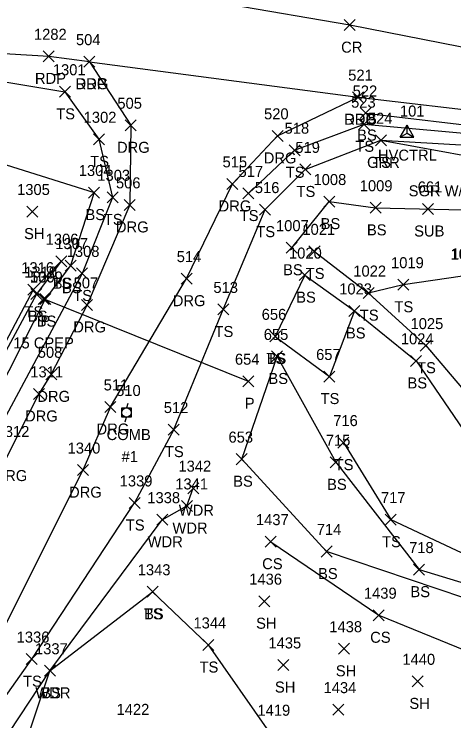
# Model space of a CAD drawing. Extents: x 1485624 to 1495982, y 886445 to 890805.
# Drawn here: x 1495597.7 to 1495677.5, y 890477.2 to 890605.4 of the extents above; entities that cross this region are included whole.
import ezdxf

# ---------------------------------------------------------------- set-up
doc = ezdxf.new("R2010")
doc.units = 0
for name, color, linetype in [('C_A', 7, 'Continuous'), ('C_I', 7, 'Continuous'), ('CPSM', 7, 'Continuous'), ('D_A', 7, 'Continuous'), ('D_C', 7, 'Continuous'), ('D_I', 7, 'Continuous'), ('D_TIC', 7, 'Continuous'), ('DCP', 7, 'Continuous'), ('L_A', 7, 'Continuous'), ('L_I', 7, 'Continuous'), ('L_TIC', 7, 'Continuous'), ('LAWA', 7, 'Continuous'), ('LELB', 7, 'Continuous'), ('P_A', 7, 'Continuous'), ('P_I', 7, 'Continuous'), ('P_TIC', 7, 'Continuous'), ('PET', 7, 'Continuous'), ('PRC', 7, 'Continuous'), ('R_A', 7, 'Continuous'), ('R_C', 7, 'Continuous'), ('R_I', 7, 'Continuous'), ('R_TIC', 7, 'Continuous'), ('RDG', 7, 'Continuous'), ('RGR', 7, 'Continuous'), ('U_A', 7, 'Continuous'), ('U_C', 7, 'Continuous'), ('U_I', 7, 'Continuous'), ('U_TIC', 7, 'Continuous'), ('UP', 7, 'Continuous')]:
    doc.layers.add(name, color=color, linetype=linetype)

msp = doc.modelspace()

# ---------------------------------------------------------------- linework, layer by layer
at = {"layer": 'CPSM'}
for p, q in [((1495667.79, 890583.11), (1495669.04, 890585.28)), ((1495670.29, 890583.11), (1495669.04, 890585.28)), ((1495669.04, 890583.84), (1495669.04, 890585.28)), ((1495667.79, 890583.11), (1495669.04, 890583.84)), ((1495669.04, 890583.84), (1495669.04, 890583.84)), ((1495669.04, 890583.84), (1495670.29, 890583.11)), ((1495667.79, 890583.11), (1495670.29, 890583.11))]:
    msp.add_line(p, q, dxfattribs=at)
at = {"layer": 'D_TIC'}
for points in [[(1495602.05, 890552.75), (1495604.05, 890554.75)], [(1495604.05, 890552.75), (1495602.05, 890554.75)], [(1495639.18, 890537.8), (1495641.18, 890539.8)], [(1495641.18, 890537.8), (1495639.18, 890539.8)]]:
    msp.add_lwpolyline(points, dxfattribs=at)
at = {"layer": 'DCP'}
msp.add_lwpolyline([(1495603.05, 890553.75), (1495640.18, 890538.8)], dxfattribs=at)
at = {"layer": 'L_TIC'}
for points in [[(1495605.9, 890590.34), (1495607.9, 890592.34)], [(1495607.9, 890590.34), (1495605.9, 890592.34)], [(1495660.52, 890586.48), (1495662.52, 890588.48)], [(1495662.52, 890586.48), (1495660.52, 890588.48)], [(1495660.23, 890584.45), (1495662.23, 890586.45)], [(1495662.23, 890584.45), (1495660.23, 890586.45)], [(1495612.07, 890581.71), (1495614.07, 890583.71)], [(1495614.07, 890581.71), (1495612.07, 890583.71)], [(1495663.27, 890581.53), (1495665.27, 890583.53)], [(1495665.27, 890581.53), (1495663.27, 890583.53)], [(1495647.59, 890579.73), (1495649.59, 890581.73)], [(1495649.59, 890579.73), (1495647.59, 890581.73)], [(1495649.54, 890576.25), (1495651.54, 890578.25)], [(1495651.54, 890576.25), (1495649.54, 890578.25)], [(1495611.18, 890572.05), (1495613.18, 890574.05)], [(1495613.18, 890572.05), (1495611.18, 890574.05)], [(1495639.23, 890571.88), (1495641.23, 890573.88)], [(1495641.23, 890571.88), (1495639.23, 890573.88)], [(1495614.55, 890571.18), (1495616.55, 890573.18)], [(1495616.55, 890571.18), (1495614.55, 890573.18)], [(1495653.89, 890570.41), (1495655.89, 890572.41)], [(1495655.89, 890570.41), (1495653.89, 890572.41)], [(1495642.24, 890568.95), (1495644.24, 890570.95)], [(1495644.24, 890568.95), (1495642.24, 890570.95)], [(1495642.24, 890568.95), (1495644.24, 890570.95)], [(1495644.24, 890568.95), (1495642.24, 890570.95)], [(1495662.3, 890569.28), (1495664.3, 890571.28)], [(1495664.3, 890569.28), (1495662.3, 890571.28)], [(1495599.98, 890568.6), (1495601.98, 890570.6)], [(1495601.98, 890568.6), (1495599.98, 890570.6)], [(1495647.08, 890562.04), (1495649.08, 890564.04)], [(1495649.08, 890562.04), (1495647.08, 890564.04)], [(1495651.22, 890561.37), (1495653.22, 890563.37)], [(1495653.22, 890561.37), (1495651.22, 890563.37)], [(1495605.23, 890559.58), (1495607.23, 890561.58)], [(1495607.23, 890559.58), (1495605.23, 890561.58)], [(1495605.23, 890559.58), (1495607.23, 890561.58)], [(1495607.23, 890559.58), (1495605.23, 890561.58)], [(1495606.91, 890558.78), (1495608.91, 890560.78)], [(1495608.91, 890558.78), (1495606.91, 890560.78)], [(1495609, 890557.37), (1495611, 890559.37)], [(1495611, 890557.37), (1495609, 890559.37)], [(1495649.44, 890557.06), (1495651.44, 890559.06)], [(1495651.44, 890557.06), (1495649.44, 890559.06)], [(1495667.33, 890555.32), (1495669.33, 890557.32)], [(1495669.33, 890555.32), (1495667.33, 890557.32)], [(1495600.14, 890554.41), (1495602.14, 890556.41)], [(1495602.14, 890554.41), (1495600.14, 890556.41)], [(1495600.73, 890553.61), (1495602.73, 890555.61)], [(1495602.73, 890553.61), (1495600.73, 890555.61)], [(1495661.04, 890553.8), (1495663.04, 890555.8)], [(1495663.04, 890553.8), (1495661.04, 890555.8)], [(1495661.04, 890553.8), (1495663.04, 890555.8)], [(1495663.04, 890553.8), (1495661.04, 890555.8)], [(1495602.33, 890552.72), (1495604.33, 890554.72)], [(1495604.33, 890552.72), (1495602.33, 890554.72)], [(1495634.65, 890550.83), (1495636.65, 890552.83)], [(1495636.65, 890550.83), (1495634.65, 890552.83)], [(1495658.47, 890550.56), (1495660.47, 890552.56)], [(1495660.47, 890550.56), (1495658.47, 890552.56)], [(1495644.09, 890545.94), (1495646.09, 890547.94)], [(1495646.09, 890545.94), (1495644.09, 890547.94)], [(1495644.09, 890545.94), (1495646.09, 890547.94)], [(1495646.09, 890545.94), (1495644.09, 890547.94)], [(1495671.43, 890544.26), (1495673.43, 890546.26)], [(1495673.43, 890544.26), (1495671.43, 890546.26)], [(1495644.41, 890542.3), (1495646.41, 890544.3)], [(1495646.41, 890542.3), (1495644.41, 890544.3)], [(1495669.67, 890541.5), (1495671.67, 890543.5)], [(1495671.67, 890541.5), (1495669.67, 890543.5)], [(1495653.92, 890538.66), (1495655.92, 890540.66)], [(1495655.92, 890538.66), (1495653.92, 890540.66)], [(1495625.65, 890529.03), (1495627.65, 890531.03)], [(1495627.65, 890529.03), (1495625.65, 890531.03)], [(1495656.47, 890526.66), (1495658.47, 890528.66)], [(1495658.47, 890526.66), (1495656.47, 890528.66)], [(1495638, 890523.66), (1495640, 890525.66)], [(1495640, 890523.66), (1495638, 890525.66)], [(1495638, 890523.66), (1495640, 890525.66)], [(1495640, 890523.66), (1495638, 890525.66)], [(1495655.07, 890523.09), (1495657.07, 890525.09)], [(1495657.07, 890523.09), (1495655.07, 890525.09)], [(1495629.21, 890518.39), (1495631.21, 890520.39)], [(1495631.21, 890518.39), (1495629.21, 890520.39)], [(1495618.54, 890515.71), (1495620.54, 890517.71)], [(1495620.54, 890515.71), (1495618.54, 890517.71)], [(1495628.05, 890515.16), (1495630.05, 890517.16)], [(1495630.05, 890515.16), (1495628.05, 890517.16)], [(1495623.56, 890512.67), (1495625.56, 890514.67)], [(1495625.56, 890512.67), (1495623.56, 890514.67)], [(1495665.08, 890512.68), (1495667.08, 890514.68)], [(1495667.08, 890512.68), (1495665.08, 890514.68)], [(1495643.28, 890508.68), (1495645.28, 890510.68)], [(1495645.28, 890508.68), (1495643.28, 890510.68)], [(1495653.42, 890506.9), (1495655.42, 890508.9)], [(1495655.42, 890506.9), (1495653.42, 890508.9)], [(1495653.42, 890506.9), (1495655.42, 890508.9)], [(1495655.42, 890506.9), (1495653.42, 890508.9)], [(1495670.2, 890503.61), (1495672.2, 890505.61)], [(1495672.2, 890503.61), (1495670.2, 890505.61)], [(1495621.82, 890499.59), (1495623.82, 890501.59)], [(1495623.82, 890499.59), (1495621.82, 890501.59)], [(1495621.82, 890499.59), (1495623.82, 890501.59)], [(1495623.82, 890499.59), (1495621.82, 890501.59)], [(1495642.12, 890497.88), (1495644.12, 890499.88)], [(1495644.12, 890497.88), (1495642.12, 890499.88)], [(1495662.89, 890495.33), (1495664.89, 890497.33)], [(1495664.89, 890495.33), (1495662.89, 890497.33)], [(1495631.93, 890489.93), (1495633.93, 890491.93)], [(1495633.93, 890489.93), (1495631.93, 890491.93)], [(1495656.6, 890489.25), (1495658.6, 890491.25)], [(1495658.6, 890489.25), (1495656.6, 890491.25)], [(1495599.88, 890487.37), (1495601.88, 890489.37)], [(1495601.88, 890487.37), (1495599.88, 890489.37)], [(1495645.54, 890486.3), (1495647.54, 890488.3)], [(1495647.54, 890486.3), (1495645.54, 890488.3)], [(1495603.16, 890485.25), (1495605.16, 890487.25)], [(1495605.16, 890485.25), (1495603.16, 890487.25)], [(1495603.16, 890485.25), (1495605.16, 890487.25)], [(1495605.16, 890485.25), (1495603.16, 890487.25)], [(1495669.96, 890483.33), (1495671.96, 890485.33)], [(1495671.96, 890483.33), (1495669.96, 890485.33)], [(1495655.57, 890478.19), (1495657.57, 890480.19)], [(1495657.57, 890478.19), (1495655.57, 890480.19)]]:
    msp.add_lwpolyline(points, dxfattribs=at)
at = {"layer": 'LAWA'}
msp.add_lwpolyline([(1495593.77, 890455.29), (1495604.16, 890486.25), (1495624.56, 890513.67), (1495629.05, 890516.16), (1495630.21, 890519.39)], dxfattribs=at)
at = {"layer": 'LELB'}
for points in [[(1495490.02, 890593.49), (1495517.04, 890595.05), (1495546.88, 890595.72), (1495587.58, 890594.51), (1495606.9, 890591.34), (1495613.07, 890582.71), (1495615.55, 890572.18), (1495610, 890558.37), (1495592.88, 890526.49), (1495577.8, 890499.74), (1495564.37, 890470.63)], [(1495491.22, 890587.26), (1495516.29, 890586.39), (1495547.35, 890588.58), (1495580.2, 890583.12), (1495612.18, 890573.05), (1495607.91, 890559.78), (1495603.33, 890553.72), (1495590.06, 890527.67), (1495576, 890500.47), (1495561.43, 890471.67)], [(1495661.52, 890587.48), (1495685.12, 890584.7), (1495703.82, 890581.92), (1495734.08, 890574), (1495763.24, 890565.13), (1495792.96, 890554.55)], [(1495640.23, 890572.88), (1495648.59, 890580.73), (1495661.23, 890585.45), (1495684.75, 890583.37), (1495703.16, 890579.81), (1495734, 890573.11), (1495763.03, 890564.51), (1495792.96, 890554.55)], [(1495643.24, 890569.95), (1495650.54, 890577.25), (1495664.27, 890582.53), (1495690.14, 890577.82), (1495701.7, 890574.71), (1495732.13, 890567.79), (1495761.45, 890557.4), (1495788.87, 890547.86), (1495821.91, 890535.22), (1495855.28, 890520.02)], [(1495648.08, 890563.04), (1495654.89, 890571.41), (1495663.3, 890570.28), (1495684.61, 890569.8), (1495706.27, 890563.36), (1495726.08, 890556.74), (1495739.05, 890554.91)], [(1495626.65, 890530.03), (1495635.65, 890551.83), (1495643.24, 890569.95)], [(1495652.22, 890562.37), (1495662.04, 890554.8)], [(1495606.23, 890560.58), (1495601.14, 890555.41), (1495586.75, 890528.42), (1495573.49, 890501.46), (1495559.15, 890472.78)], [(1495606.23, 890560.58), (1495601.73, 890554.61), (1495587.51, 890528.3), (1495574.69, 890500.59), (1495560.18, 890472.05)], [(1495650.44, 890558.06), (1495645.09, 890546.94)], [(1495650.44, 890558.06), (1495659.47, 890551.56), (1495670.67, 890542.5), (1495680.95, 890527.45), (1495694.72, 890514.02), (1495701.89, 890508.36)], [(1495739.03, 890547.65), (1495724.1, 890552.5), (1495699.75, 890551.1), (1495679.27, 890557.9), (1495679.11, 890557.89), (1495668.33, 890556.32), (1495662.04, 890554.8), (1495672.43, 890545.26), (1495683.67, 890532.06), (1495695.19, 890516.26), (1495707.45, 890511.95), (1495709.18, 890508.83), (1495715.54, 890502.47), (1495718.87, 890501.79), (1495723.73, 890502.35)], [(1495659.47, 890551.56), (1495654.92, 890539.66)], [(1495645.09, 890546.94), (1495654.92, 890539.66)], [(1495639, 890524.66), (1495645.41, 890543.3), (1495656.07, 890524.09), (1495671.2, 890504.61), (1495691.33, 890498.5), (1495709.49, 890487.2)], [(1495626.65, 890530.03), (1495619.54, 890516.71)], [(1495657.47, 890527.66), (1495666.08, 890513.68), (1495691.78, 890501.67), (1495709.49, 890487.2)], [(1495639, 890524.66), (1495654.42, 890507.9)], [(1495581.23, 890460.57), (1495600.88, 890488.37), (1495619.54, 890516.71)], [(1495644.28, 890509.68), (1495663.89, 890496.33), (1495679.64, 890489.96), (1495689.21, 890481.51), (1495701.43, 890473.38), (1495703.96, 890466.13), (1495674.38, 890457.51)], [(1495714.75, 890472.6), (1495705.34, 890483.1), (1495679.51, 890499.41), (1495654.42, 890507.9)], [(1495585.72, 890458.37), (1495604.16, 890486.25), (1495622.82, 890500.59)], [(1495622.82, 890500.59), (1495632.93, 890490.93), (1495643.99, 890475.09), (1495644.06, 890464.76), (1495641.37, 890459.39), (1495636.68, 890447.23), (1495634.38, 890435.24)]]:
    msp.add_lwpolyline(points, dxfattribs=at)
at = {"layer": 'P_TIC'}
for points in [[(1495657.63, 890602.44), (1495659.63, 890604.44)], [(1495659.63, 890602.44), (1495657.63, 890604.44)], [(1495602.97, 890596.77), (1495604.97, 890598.77)], [(1495604.97, 890596.77), (1495602.97, 890598.77)], [(1495610.34, 890595.8), (1495612.34, 890597.8)], [(1495612.34, 890595.8), (1495610.34, 890597.8)], [(1495659.14, 890589.36), (1495661.14, 890591.36)], [(1495661.14, 890589.36), (1495659.14, 890591.36)]]:
    msp.add_lwpolyline(points, dxfattribs=at)
at = {"layer": 'PET'}
for points in [[(1495603.97, 890597.77), (1495580.62, 890599.12), (1495545.48, 890599.22), (1495516.97, 890597.78), (1495489.95, 890595.44)], [(1495611.34, 890596.8), (1495660.14, 890590.36), (1495685.99, 890587.32), (1495704.29, 890583.39), (1495734.68, 890576.01), (1495763.96, 890566.85), (1495794.17, 890556.56), (1495823.36, 890544.58), (1495859.75, 890527.82)]]:
    msp.add_lwpolyline(points, dxfattribs=at)
at = {"layer": 'PRC'}
msp.add_lwpolyline([(1495865.85, 890538.25), (1495835.89, 890551.78), (1495804.87, 890564.57), (1495770.54, 890576.59), (1495737.23, 890586.26), (1495702.08, 890594.9), (1495658.63, 890603.44), (1495614.66, 890611.01)], dxfattribs=at)
at = {"layer": 'R_TIC'}
for points in [[(1495610.34, 890595.8), (1495612.34, 890597.8)], [(1495612.34, 890595.8), (1495610.34, 890597.8)], [(1495659.14, 890589.36), (1495661.14, 890591.36)], [(1495661.14, 890589.36), (1495659.14, 890591.36)], [(1495617.86, 890584.26), (1495619.86, 890586.26)], [(1495619.86, 890584.26), (1495617.86, 890586.26)], [(1495644.51, 890582.34), (1495646.51, 890584.34)], [(1495646.51, 890582.34), (1495644.51, 890584.34)], [(1495663.27, 890581.53), (1495665.27, 890583.53)], [(1495665.27, 890581.53), (1495663.27, 890583.53)], [(1495636.32, 890573.62), (1495638.32, 890575.62)], [(1495638.32, 890573.62), (1495636.32, 890575.62)], [(1495617.66, 890569.81), (1495619.66, 890571.81)], [(1495619.66, 890569.81), (1495617.66, 890571.81)], [(1495628, 890556.42), (1495630, 890558.42)], [(1495630, 890556.42), (1495628, 890558.42)], [(1495609.92, 890551.66), (1495611.92, 890553.66)], [(1495611.92, 890551.66), (1495609.92, 890553.66)], [(1495603.4, 890539.06), (1495605.4, 890541.06)], [(1495605.4, 890539.06), (1495603.4, 890541.06)], [(1495601.16, 890535.5), (1495603.16, 890537.5)], [(1495603.16, 890535.5), (1495601.16, 890537.5)], [(1495614.15, 890533.13), (1495616.15, 890535.13)], [(1495616.15, 890533.13), (1495614.15, 890535.13)], [(1495609.16, 890521.67), (1495611.16, 890523.67)], [(1495611.16, 890521.67), (1495609.16, 890523.67)]]:
    msp.add_lwpolyline(points, dxfattribs=at)
at = {"layer": 'RDG'}
for points in [[(1495611.34, 890596.8), (1495603.97, 890597.77)], [(1495611.34, 890596.8), (1495618.86, 890585.26), (1495618.66, 890570.81), (1495610.92, 890552.66), (1495604.4, 890540.06)], [(1495615.15, 890534.13), (1495629, 890557.42), (1495637.32, 890574.62), (1495645.51, 890583.34), (1495660.14, 890590.36)], [(1495604.4, 890540.06), (1495602.16, 890536.5)], [(1495602.16, 890536.5), (1495596.62, 890525.68), (1495582.8, 890496.65), (1495568.96, 890468.31)], [(1495615.15, 890534.13), (1495610.16, 890522.67)], [(1495578.98, 890461.27), (1495594.1, 890490.63), (1495610.16, 890522.67)]]:
    msp.add_lwpolyline(points, dxfattribs=at)
at = {"layer": 'RGR'}
msp.add_lwpolyline([(1495664.27, 890582.53), (1495685.11, 890581.37), (1495702.59, 890578.48), (1495733.01, 890569.82), (1495762.5, 890560.97), (1495791.3, 890551.45), (1495822.57, 890539.06), (1495857.36, 890523.4), (1495878.61, 890513.19), (1495895.11, 890505.02), (1495906, 890498.67), (1495922.02, 890487.12)], dxfattribs=at)
at = {"layer": 'U_TIC'}
for points in [[(1495671.85, 890569.07), (1495673.85, 890571.07)], [(1495673.85, 890569.07), (1495671.85, 890571.07)]]:
    msp.add_lwpolyline(points, dxfattribs=at)
at = {"layer": 'UP'}
for p, q in [((1495617.24, 890532.29), (1495617.24, 890533.95)), ((1495617.24, 890533.95), (1495618.91, 890533.95)), ((1495618.33, 890534.79), (1495618.08, 890533.95)), ((1495618.91, 890533.95), (1495618.91, 890532.29)), ((1495618.91, 890532.29), (1495617.24, 890532.29)), ((1495617.83, 890531.45), (1495618.08, 890532.29)), ((1495618.08, 890533.12), (1495618.08, 890533.12))]:
    msp.add_line(p, q, dxfattribs=at)
msp.add_circle((1495618.08, 890533.12), 0.833, dxfattribs=at)

# ---------------------------------------------------------------- texts
at = {"layer": 'C_A'}
msp.add_text('HVCTRL', height=2, dxfattribs=at).set_placement((1495663.74, 890578.84))
at = {"layer": 'C_I'}
msp.add_text('101', height=2, dxfattribs=at).set_placement((1495667.74, 890586.84))
at = {"layer": 'D_A'}
for p in [(1495602.43, 890548.75), (1495639.56, 890533.8)]:
    msp.add_text('P', height=2, dxfattribs=at).set_placement(p)
at = {"layer": 'D_C'}
msp.add_text('15 CPEP', height=2, dxfattribs=at).set_placement((1495597.52, 890544.75))
at = {"layer": 'D_I'}
for s, p in [('509', (1495600.6, 890556.75)), ('654', (1495637.77, 890541.8))]:
    msp.add_text(s, height=2, dxfattribs=at).set_placement(p)
at = {"layer": 'L_A'}
for s, p in [('TS', (1495605.31, 890586.34)), ('BS', (1495659.96, 890582.48)), ('TS', (1495659.64, 890580.45)), ('TS', (1495611.48, 890577.71)), ('TS', (1495662.68, 890577.53)), ('TS', (1495647, 890575.73)), ('TS', (1495648.95, 890572.25)), ('BS', (1495610.62, 890568.05)), ('TS', (1495638.64, 890567.88)), ('TS', (1495613.96, 890567.18)), ('BS', (1495653.33, 890566.41)), ('TS', (1495641.65, 890564.95)), ('TS', (1495641.65, 890564.95)), ('BS', (1495661.74, 890565.28)), ('SH', (1495599.47, 890564.6)), ('BS', (1495646.52, 890558.04)), ('TS', (1495650.63, 890557.37)), ('TS', (1495604.64, 890555.58)), ('BS', (1495604.67, 890555.58)), ('BS', (1495606.35, 890554.78)), ('TS', (1495608.4, 890553.37)), ('BS', (1495648.89, 890553.06)), ('TS', (1495666.74, 890551.32)), ('TS', (1495599.55, 890550.41)), ('BS', (1495600.17, 890549.61)), ('TS', (1495660.45, 890549.8)), ('TS', (1495660.45, 890549.8)), ('BS', (1495601.77, 890548.72)), ('TS', (1495634.06, 890546.83)), ('BS', (1495657.92, 890546.56)), ('TS', (1495643.5, 890541.94)), ('BS', (1495643.53, 890541.94)), ('TS', (1495670.84, 890540.26)), ('BS', (1495643.85, 890538.3)), ('BS', (1495669.11, 890537.5)), ('TS', (1495653.32, 890534.66)), ('TS', (1495625.06, 890525.03)), ('TS', (1495655.88, 890522.66)), ('BS', (1495637.45, 890519.66)), ('BS', (1495637.45, 890519.66)), ('BS', (1495654.51, 890519.09)), ('WDR', (1495627.57, 890514.39)), ('TS', (1495617.95, 890511.71)), ('WDR', (1495626.42, 890511.16)), ('WDR', (1495621.92, 890508.67)), ('TS', (1495664.49, 890508.68)), ('CS', (1495642.72, 890504.68)), ('BS', (1495652.86, 890502.9)), ('BS', (1495652.86, 890502.9)), ('BS', (1495669.64, 890499.61)), ('TS', (1495621.23, 890495.59)), ('BS', (1495621.26, 890495.59)), ('SH', (1495641.61, 890493.88)), ('CS', (1495662.33, 890491.33)), ('TS', (1495631.34, 890485.93)), ('SH', (1495656.09, 890485.25)), ('TS', (1495599.29, 890483.37)), ('SH', (1495645.03, 890482.3)), ('WDR', (1495601.52, 890481.25)), ('BS', (1495602.6, 890481.25)), ('SH', (1495669.45, 890479.33))]:
    msp.add_text(s, height=2, dxfattribs=at).set_placement(p)
at = {"layer": 'L_I'}
for s, p in [('1301', (1495604.7, 890594.34)), ('522', (1495659.15, 890590.48)), ('523', (1495658.87, 890588.45)), ('1302', (1495610.3, 890585.71)), ('524', (1495661.91, 890585.53)), ('518', (1495646.79, 890583.73)), ('519', (1495648.74, 890580.25)), ('1304', (1495609.41, 890576.05)), ('1303', (1495612.78, 890575.18)), ('517', (1495638.43, 890575.88)), ('1008', (1495652.04, 890574.41)), ('1305', (1495598.21, 890572.6)), ('516', (1495641.39, 890572.95)), ('516', (1495641.39, 890572.95)), ('1009', (1495660.44, 890573.28)), ('1007', (1495645.23, 890566.04)), ('1021', (1495650.02, 890565.37)), ('1306', (1495603.4, 890563.58)), ('1306', (1495603.4, 890563.58)), ('1307', (1495605.14, 890562.78)), ('1308', (1495607.22, 890561.37)), ('1020', (1495647.59, 890561.06)), ('1018', (1495676.91, 890560.89)), ('1017', (1495677.06, 890560.9)), ('1019', (1495666.12, 890559.32)), ('1316', (1495598.96, 890558.41)), ('1310', (1495599.52, 890557.61)), ('1022', (1495659.27, 890557.8)), ('1022', (1495659.27, 890557.8)), ('1309', (1495600.55, 890556.72)), ('513', (1495633.86, 890554.83)), ('1023', (1495656.7, 890554.56)), ('656', (1495642.63, 890549.94)), ('656', (1495642.63, 890549.94)), ('1025', (1495669.66, 890548.26)), ('655', (1495643, 890546.3)), ('1024', (1495667.9, 890545.5)), ('657', (1495652.51, 890542.66)), ('512', (1495624.85, 890533.03)), ('716', (1495655.62, 890530.66)), ('653', (1495636.6, 890527.66)), ('653', (1495636.6, 890527.66)), ('715', (1495654.27, 890527.09)), ('1342', (1495627.51, 890522.39)), ('1339', (1495616.84, 890519.71)), ('1341', (1495626.93, 890519.16)), ('1338', (1495621.86, 890516.67)), ('717', (1495664.29, 890516.68)), ('1437', (1495641.59, 890512.68)), ('714', (1495652.63, 890510.9)), ('714', (1495652.63, 890510.9)), ('718', (1495669.4, 890507.61)), ('1343', (1495620.12, 890503.59)), ('1343', (1495620.12, 890503.59)), ('1436', (1495640.37, 890501.88)), ('1439', (1495661.19, 890499.33)), ('1344', (1495630.24, 890493.93)), ('1438', (1495654.91, 890493.25)), ('1336', (1495598.13, 890491.37)), ('1337', (1495601.46, 890489.25)), ('1337', (1495601.46, 890489.25)), ('1435', (1495643.85, 890490.3)), ('1440', (1495668.18, 890487.33)), ('1434', (1495653.87, 890482.19)), ('1422', (1495616.27, 890478.25)), ('1419', (1495641.86, 890478.09))]:
    msp.add_text(s, height=2, dxfattribs=at).set_placement(p)
at = {"layer": 'P_A'}
for s, p in [('CR', (1495657.06, 890598.44)), ('RDP', (1495601.45, 890592.77)), ('RDP', (1495608.83, 890591.8)), ('RDP', (1495657.62, 890585.36))]:
    msp.add_text(s, height=2, dxfattribs=at).set_placement(p)
at = {"layer": 'P_I'}
for s, p in [('1282', (1495601.27, 890600.77)), ('504', (1495608.9, 890599.8)), ('521', (1495658.34, 890593.36))]:
    msp.add_text(s, height=2, dxfattribs=at).set_placement(p)
at = {"layer": 'R_A'}
for s, p in [('DRG', (1495608.83, 890591.8)), ('DRG', (1495657.62, 890585.36)), ('DRG', (1495616.35, 890580.26)), ('DRG', (1495643, 890578.34)), ('GRR', (1495661.76, 890577.53)), ('DRG', (1495634.8, 890569.62)), ('DRG', (1495616.15, 890565.81)), ('DRG', (1495626.48, 890552.42)), ('DRG', (1495608.41, 890547.66)), ('DRG', (1495601.88, 890535.06)), ('DRG', (1495599.65, 890531.5)), ('DRG', (1495612.64, 890529.13)), ('DRG', (1495594.11, 890520.68)), ('DRG', (1495607.64, 890517.67))]:
    msp.add_text(s, height=2, dxfattribs=at).set_placement(p)
at = {"layer": 'R_C'}
msp.add_text('SGR W/STEEL POSTS', height=2, dxfattribs=at).set_placement((1495669.32, 890572.37))
at = {"layer": 'R_I'}
for s, p in [('504', (1495608.9, 890599.8)), ('521', (1495658.34, 890593.36)), ('505', (1495616.42, 890588.26)), ('520', (1495643.06, 890586.34)), ('524', (1495661.91, 890585.53)), ('515', (1495635.52, 890577.62)), ('506', (1495616.16, 890573.81)), ('514', (1495627.2, 890560.42)), ('507', (1495608.48, 890555.66)), ('508', (1495601.96, 890543.06)), ('1311', (1495600.6, 890539.5)), ('511', (1495613.93, 890537.13)), ('1312', (1495594.49, 890528.68)), ('1340', (1495607.38, 890525.67))]:
    msp.add_text(s, height=2, dxfattribs=at).set_placement(p)
at = {"layer": 'U_A'}
for s, p in [('SUB', (1495670.32, 890565.07)), ('COMB', (1495614.46, 890528.12))]:
    msp.add_text(s, height=2, dxfattribs=at).set_placement(p)
at = {"layer": 'U_C'}
msp.add_text('#1', height=2, dxfattribs=at).set_placement((1495617.18, 890524.12))
at = {"layer": 'U_I'}
for s, p in [('661', (1495670.96, 890573.07)), ('510', (1495616.2, 890536.12))]:
    msp.add_text(s, height=2, dxfattribs=at).set_placement(p)

doc.saveas('drawing.dxf')
